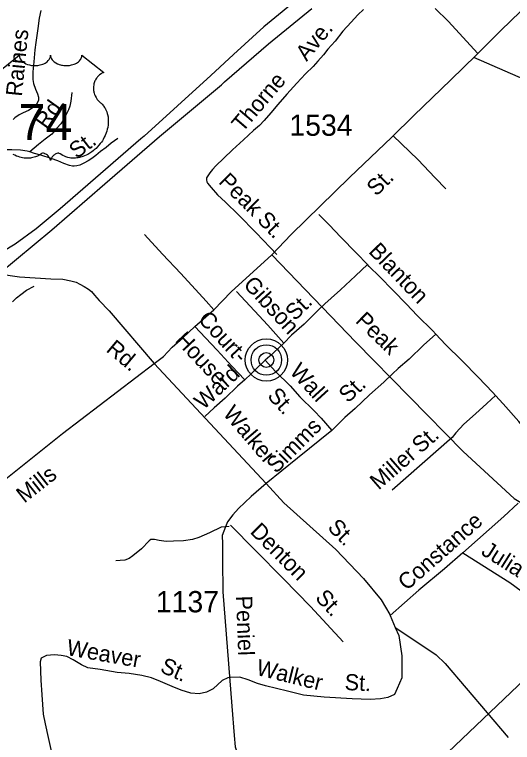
# Model space of a CAD drawing. Extents: x 990631 to 1056237, y 535999 to 585651.
# Drawn here: x 1044054 to 1046984, y 559473 to 563754 of the extents above; entities that cross this region are included whole.
import ezdxf

# ---------------------------------------------------------------- set-up
doc = ezdxf.new("R2010")
doc.units = 0
for name, color, linetype in [('Exist Boundary Political City Limit New', 7, 'Continuous'), ('Exist Civil Demographics County Seat CELL', 7, 'Continuous'), ('Exist Road Non-System Type 51', 7, 'Continuous'), ('Exist Road Non-System Type 51 Label', 7, 'Continuous'), ('Exist Road Primary NC Attributed', 7, 'Continuous'), ('Exist Road Primary NC Label', 7, 'Continuous'), ('Exist Road Primary US Divided Attributed', 7, 'Continuous'), ('Exist Road Primary US Shield CELL', 7, 'Continuous'), ('Exist Road Primary US Shield Number Label', 7, 'Continuous'), ('Exist Road Secondary Type 51 Attributed', 7, 'Continuous'), ('Exist Road Secondary Type 51 Label', 7, 'Continuous'), ('Exist Road Secondary Type 51 Number Label', 7, 'Continuous')]:
    doc.layers.add(name, color=color, linetype=linetype)

msp = doc.modelspace()

# ---------------------------------------------------------------- linework, layer by layer
at = {"layer": 'Exist Boundary Political City Limit New'}
msp.add_lwpolyline([(1047556.4, 560320.3), (1045570.9, 558429)], dxfattribs=at)
at = {"layer": 'Exist Civil Demographics County Seat CELL'}
for radius in [124.7, 90, 43.3]:
    msp.add_circle((1045536.1, 561722.3), radius, dxfattribs=at)
at = {"layer": 'Exist Road Non-System Type 51'}
for p, q in [((1046630.2, 561266.3), (1046276.1, 560957.5)), ((1046264.4, 560219.2), (1046294.2, 560148.2))]:
    msp.add_line(p, q, dxfattribs=at)
for points in [[(1046108.7, 563783.7), (1046073.7, 563752.8), (1046036.2, 563710), (1045986.5, 563655.5), (1045940.5, 563597), (1045898.9, 563550.3), (1045871.9, 563517.2), (1045838.7, 563480), (1045811.7, 563449), (1045766.2, 563404.5), (1045716.4, 563350), (1045656.3, 563285.8), (1045604.5, 563225.5), (1045562.9, 563176.7), (1045523.4, 563130), (1045496.4, 563100.8), (1045461.4, 563071.9), (1045401.7, 563017.8), (1045337.6, 562957.9), (1045286, 562909.5), (1045238.5, 562864.9), (1045219.9, 562843.4), (1045203.3, 562824), (1045188.6, 562800.4), (1045184.3, 562792.7), (1045184.1, 562782.7), (1045185.6, 562770.5), (1045189.3, 562762.4), (1045210.5, 562735.8), (1045249.1, 562694.6), (1045295.9, 562651), (1045371.4, 562576.5), (1045476.1, 562471.1), (1045559.4, 562384.2), (1045598.2, 562343)], [(1046780.6, 563524.3), (1046606.7, 563715.7), (1046529.2, 563790.3)], [(1044209.2, 563778.5), (1044199.8, 563732.9), (1044191.8, 563671), (1044179.2, 563589.4), (1044173.9, 563545.5), (1044167.5, 563475.6), (1044161.7, 563417.9), (1044162.2, 563371.9), (1044165.5, 563347.6), (1044178.4, 563315.1), (1044189.5, 563286.9), (1044194.9, 563268.6), (1044196.3, 563250.6), (1044189.9, 563236.9), (1044181.4, 563223), (1044169.1, 563211.5), (1044136.3, 563190.5), (1044105.8, 563175.5), (1044081.6, 563164.2), (1044056.8, 563147.1), (1044046.6, 563137.3)], [(1047929.9, 562160.1), (1047925.6, 562278.4), (1047914.2, 562426.9), (1047906.6, 562495.1), (1047901.4, 562527.4), (1047888.5, 562559.9), (1047868.4, 562614.5), (1047848.1, 562669.2), (1047825.6, 562717.8), (1047793.2, 562766.9), (1047756.8, 562816.2), (1047722.1, 562861.4), (1047695.1, 562890.3), (1047644.6, 562939.9), (1047587.9, 562985.7), (1047515.9, 563044.2), (1047437.7, 563106.6), (1047379.6, 563160.6), (1047319, 563210.6), (1047254.5, 563258.7), (1047207.6, 563294.1), (1047172.5, 563317.2), (1047125.1, 563340.7), (1046757.3, 563501.6)], [(1044391.9, 563296.4), (1044386.3, 563244.5), (1044379.3, 563214.7), (1044372.6, 563193), (1044357.7, 563165.5), (1044344.7, 563137.7), (1044326, 563110.3), (1044303.1, 563085.2), (1044273.9, 563049.9), (1044234.9, 563021.3), (1044195.9, 562990.5), (1044169.2, 562967.2), (1044144.6, 562946.1)], [(1044661.4, 563025.5), (1044622.4, 562996.9), (1044593.7, 562971.7), (1044560.8, 562948.7), (1044532.1, 562925.7), (1044509.6, 562908.3), (1044487.1, 562893), (1044462.6, 562879.9), (1044438.1, 562868.6), (1044420.1, 562865.1), (1044406, 562861.6), (1044396, 562862), (1044378.1, 562866.6), (1044344.5, 562877.6), (1044309, 562892.8), (1044269.5, 562908), (1044210, 562926), (1044172.2, 562937.1), (1044144.6, 562946.1)], [(1046593.1, 562729.4), (1046529.1, 562793.5), (1046426.7, 562900.8), (1046282.9, 563040.9)], [(1044144.6, 562946.1), (1044128.7, 562950.6), (1044088.8, 562955.8), (1044038.8, 562957.4), (1043992.8, 562958.9)], [(1046130.6, 562283.9), (1046066.7, 562350), (1045971.8, 562447.2), (1045907.9, 562515.3), (1045845.8, 562577.4)], [(1045227.6, 562017.3), (1045181.1, 562068.3), (1045032.1, 562231.2), (1044925.8, 562344.6), (1044819.5, 562460.1)], [(1046130.6, 562283.9), (1046060.4, 562218.1), (1045971.7, 562134.9), (1045918.1, 562086.7), (1045881, 562051.8)], [(1046533.7, 561874.7), (1046516.2, 561893.4), (1046423.2, 561984.3), (1046361.3, 562050.4), (1046281.7, 562131), (1046202.4, 562213.7), (1046142.1, 562271.5), (1046130.6, 562283.9)], [(1044042.3, 562064.8), (1044066.9, 562087.9), (1044091.5, 562107.2), (1044124.4, 562132.2), (1044169, 562156.5)], [(1045639.5, 561821.4), (1045544.8, 561926.6), (1045467.4, 562010.9), (1045360.9, 562124.5)], [(1045881, 562051.8), (1045839.8, 562013.1), (1045759.2, 561933.7), (1045685, 561867.9), (1045639.5, 561821.4)], [(1045410.5, 561606.5), (1045332.8, 561685.1), (1045245.9, 561779.9), (1045178.2, 561852.1), (1045114.7, 561918.4)], [(1046533.7, 561874.7), (1046461.5, 561809.1), (1046376.9, 561727.8), (1046311.1, 561671.7), (1046278.1, 561640.7)], [(1046884.3, 561513.3), (1046868.9, 561531.8), (1046781.8, 561620.6), (1046688.8, 561717.7), (1046589.8, 561812.9), (1046533.7, 561874.7)], [(1045639.5, 561821.4), (1045608.5, 561792.4), (1045556.9, 561744), (1045530, 561720.8)], [(1045530, 561720.8), (1045480.7, 561674.4), (1045447.6, 561641.4), (1045410.5, 561606.5)], [(1045530, 561720.8), (1045590.1, 561654.7), (1045675.4, 561570), (1045733.4, 561506.2), (1045816.7, 561423.5), (1045859.5, 561380), (1045921, 561307.4)], [(1045410.5, 561606.5), (1045367.1, 561568), (1045292.9, 561498.3), (1045228.9, 561440.3), (1045174.7, 561389.5)], [(1046278.1, 561640.7), (1046228.5, 561592.3), (1046143.9, 561517), (1046059.3, 561437.6), (1045997.6, 561383.7), (1045921, 561307.4)], [(1046884.3, 561513.3), (1046832.8, 561466.9), (1046766.9, 561405), (1046698.9, 561345.1), (1046651.3, 561293.2), (1046630.2, 561266.3)], [(1047265.7, 561109.8), (1047202.5, 561139.9), (1047144.7, 561211.7), (1047089.1, 561278.9), (1047021.5, 561360.7), (1046930.7, 561463.7), (1046884.3, 561513.3)], [(1045921, 561307.4), (1045720.1, 561145.2), (1045534.2, 560996.2)], [(1045534.2, 560996.2), (1045639.2, 560881.4), (1045944.7, 560607.8), (1046107.3, 560436.5), (1046211.3, 560311.2), (1046262.5, 560225.3), (1046264.4, 560219.2)], [(1047018.2, 560879.5), (1046933.6, 560802.2), (1046692.6, 560587.8)], [(1045989.2, 560063.9), (1045795.7, 560272.3), (1045637, 560435.6), (1045470.3, 560603), (1045324.8, 560751.8)], [(1045316.6, 560742.1), (1045270.4, 560739.5), (1045201.3, 560705.6), (1045138.5, 560677.7), (1045102, 560666.8), (1045047.7, 560658.7), (1044989.6, 560656.5), (1044947.6, 560655.7), (1044905.7, 560661.2), (1044877.8, 560666.1), (1044855.8, 560666.8), (1044847.6, 560659.1), (1044802, 560612.4), (1044750.8, 560570.1), (1044728.1, 560554.7), (1044703.9, 560545.6), (1044675.8, 560542.4), (1044649.8, 560541.3)], [(1046692.6, 560587.8), (1046585.5, 560493.3), (1046433.3, 560368.1), (1046264.4, 560219.2)], [(1046692.6, 560587.8), (1046969.2, 560412.9), (1047102.1, 560316.6), (1047147.4, 560293.1), (1047213.1, 560285), (1047317.4, 560287.7), (1047365.6, 560298.1), (1047418.5, 560322.5), (1047451.1, 560341.4)], [(1046294.2, 560148.2), (1046316.7, 560101.6), (1046332.9, 559983), (1046332.7, 559852.9), (1046306.6, 559789.6), (1046289.5, 559754.2), (1046250.9, 559737.3), (1046208.7, 559728.8), (1046146.4, 559724.8), (1046040.7, 559730.2), (1045876.8, 559739.5), (1045755, 559751.3), (1045659.9, 559774.5), (1045530.7, 559806.5), (1045485.1, 559820), (1045429.7, 559841.7), (1045380.2, 559857.3), (1045326.2, 559855.2)], [(1046294.2, 560148.2), (1046451, 560045.2), (1046535.3, 559988.5), (1046587.6, 559936.8), (1046959.8, 559502.6)], [(1045326.2, 559855.2), (1045310.1, 559853.7), (1045275.6, 559836.8), (1045224, 559788.4), (1045183.2, 559769.7), (1045141, 559759.1), (1045091, 559762.7), (1045035.6, 559780.4), (1044982.2, 559802.1), (1044913.2, 559832.3), (1044859.7, 559852.2), (1044804.2, 559865.9), (1044728.4, 559878.2), (1044658.5, 559884.5), (1044559, 559901.9), (1044485.4, 559912.2), (1044448, 559929.3), (1044398.9, 559958.9), (1044361.5, 559978.1), (1044329.6, 559985.1), (1044289.7, 559988.5), (1044241.6, 559984.1), (1044211.1, 559968.9), (1044204.4, 559947.2), (1044208.9, 559838.9), (1044214.1, 559752.8), (1044222.5, 559640.3), (1044234.7, 559581.9), (1044252.1, 559501.3), (1044271.3, 559414.7)]]:
    msp.add_lwpolyline(points, dxfattribs=at)
at = {"layer": 'Exist Road Primary NC Attributed'}
for points in [[(1045567.7, 562340.2), (1045682.5, 562460.5), (1046025, 562795.1), (1046274.5, 563032.6), (1046404.6, 563160.8), (1046621.7, 563370.6), (1046771.4, 563515), (1046901.5, 563647.2), (1046989.2, 563730.8), (1047131.4, 563866.4), (1047185.4, 563916.4), (1047237.5, 563962.6)], [(1044875.9, 561701), (1044930.6, 561743.3), (1044982.7, 561798.2), (1045045.6, 561852.1), (1045114.7, 561918.4), (1045227.6, 562017.3), (1045330.1, 562124.1), (1045567.7, 562340.2)], [(1043264.1, 560006.8), (1043301.1, 560087.7), (1043356.2, 560202.3), (1043396.6, 560300.1), (1043465.9, 560437.4), (1043488.5, 560482.8), (1043571.2, 560612), (1043623.3, 560676.2), (1043729.6, 560794.1), (1043834.2, 560890.3), (1044336.7, 561290.9), (1044875.9, 561701)]]:
    msp.add_lwpolyline(points, dxfattribs=at)
at = {"layer": 'Exist Road Primary US Divided Attributed'}
for points in [[(1045749.4, 563870.6), (1045521.5, 563680.7), (1045342.9, 563519.8), (1045208.9, 563394.6), (1044818, 563039.3), (1044797.9, 563023.6), (1044322.5, 562611.4), (1044182.1, 562494), (1044059, 562403.5), (1043823.6, 562261.7)], [(1043960.7, 562229.1), (1044274.8, 562488.4), (1044585.7, 562757.7), (1044907.3, 563037.1), (1045271.4, 563341), (1045289.3, 563358.9), (1045548.3, 563582.4), (1045803, 563790.2)]]:
    msp.add_lwpolyline(points, dxfattribs=at)
at = {"layer": 'Exist Road Primary US Shield CELL'}
msp.add_lwpolyline([(1043953.8, 563412.5), (1044082.4, 563515), (1044082.7, 563509.6), (1044084, 563503.3), (1044085, 563500.1), (1044088, 563493.8), (1044092.8, 563486.5), (1044099.6, 563479.3), (1044107.3, 563472.9), (1044112.4, 563469.6), (1044121.2, 563464.9), (1044131.2, 563460.7), (1044142.3, 563457.5), (1044153.6, 563455.2), (1044165.9, 563453.9), (1044178.2, 563453.6), (1044191.4, 563454.6), (1044206, 563457.4), (1044212.7, 563459.2), (1044220.3, 563461.8), (1044227.2, 563464.7), (1044234.9, 563468.8), (1044241.1, 563472.7), (1044245.9, 563476.2), (1044252.7, 563482.7), (1044258.2, 563489.5), (1044260.4, 563493.3), (1044262.4, 563497), (1044265.1, 563504.7), (1044265.9, 563508.1), (1044266.4, 563515.2), (1044266.8, 563509.3), (1044267.5, 563505.5), (1044268.4, 563501.9), (1044270, 563498), (1044272.7, 563492.5), (1044275.7, 563488), (1044281.5, 563481.2), (1044285, 563477.9), (1044288.3, 563475.2), (1044297, 563469.2), (1044307.2, 563464.1), (1044312.3, 563461.9), (1044317.4, 563460), (1044324, 563458.1), (1044330.7, 563456.5), (1044337.4, 563455.3), (1044344.2, 563454.3), (1044351.2, 563453.8), (1044356.9, 563453.6), (1044363.9, 563453.7), (1044370.4, 563454.1), (1044377, 563454.9), (1044384.3, 563456.1), (1044390.1, 563457.4), (1044397.9, 563459.4), (1044404.8, 563461.9), (1044411, 563464.6), (1044419, 563468.8), (1044425.4, 563472.8), (1044430.1, 563476.6), (1044435.8, 563481.8), (1044441.1, 563487.9), (1044444.2, 563492.4), (1044446.4, 563497), (1044448.4, 563501.9), (1044449.7, 563507.1), (1044450.3, 563511.5), (1044450.4, 563515.4), (1044579, 563412.9), (1044576, 563411.8), (1044569, 563408.4), (1044563.5, 563405.1), (1044554.6, 563398.9), (1044550.8, 563395.4), (1044547, 563391.9), (1044543.5, 563388.1), (1044540.4, 563384.5), (1044536.7, 563379.3), (1044533.4, 563374.2), (1044530.1, 563368.5), (1044527.7, 563363.5), (1044523.8, 563353.2), (1044521.9, 563346.7), (1044520.7, 563341.1), (1044519.1, 563329.6), (1044518.8, 563324.2), (1044518.8, 563318.8), (1044519.1, 563313.1), (1044519.6, 563307.6), (1044520.6, 563301.9), (1044521.5, 563296.9), (1044523.1, 563290.7), (1044525.4, 563283.6), (1044528.2, 563276.7), (1044534.1, 563265.5), (1044541.6, 563254.1), (1044547, 563247.7), (1044552.3, 563242.2), (1044560.3, 563235.6), (1044564.6, 563231.8), (1044569.5, 563226.8), (1044577.5, 563217.5), (1044580.8, 563213.1), (1044584.1, 563208.1), (1044587.2, 563203), (1044590.2, 563197.6), (1044592.6, 563192.8), (1044597.1, 563181.8), (1044600.4, 563171), (1044602, 563165.4), (1044604.4, 563152.8), (1044605.3, 563146.6), (1044606.3, 563134.3), (1044606.3, 563119.4), (1044605.2, 563105.2), (1044602.5, 563088.8), (1044600.3, 563078.9), (1044596.9, 563067.4), (1044593.6, 563057.4), (1044587.8, 563042.8), (1044582.6, 563032.1), (1044575.8, 563019.7), (1044571.2, 563012.2), (1044565.8, 563004.1), (1044559, 562994.8), (1044551.1, 562985), (1044541.6, 562974.5), (1044534, 562966.9), (1044523.9, 562957.9), (1044517.9, 562952.9), (1044509.2, 562946.4), (1044497.3, 562938.5), (1044485.7, 562931.7), (1044475.7, 562926.6), (1044466.9, 562922.8), (1044455.5, 562918.5), (1044436.5, 562913.2), (1044429.6, 562911.8), (1044421.4, 562910.6), (1044413.7, 562909.8), (1044406.3, 562909.3), (1044396.3, 562909.3), (1044386.3, 562910.1), (1044376.9, 562911.5), (1044367.1, 562913.5), (1044356.8, 562916.6), (1044347.5, 562920.2), (1044338.1, 562924.9), (1044322.2, 562934.9), (1044317.6, 562937.3), (1044315, 562938), (1044308.9, 562938.3), (1044303.1, 562937.1), (1044297.2, 562934.7), (1044293.6, 562932.8), (1044288.9, 562929.7), (1044285.2, 562926.8), (1044280.8, 562922.6), (1044277.8, 562919.1), (1044275.5, 562916.4), (1044271, 562909.3), (1044269.4, 562906), (1044267.7, 562901.7), (1044266.3, 562895.3), (1044264.2, 562903.3), (1044261.9, 562908.7), (1044259.1, 562913.2), (1044256.3, 562917.3), (1044251.8, 562922.4), (1044247.8, 562926.3), (1044242.9, 562930.2), (1044237.8, 562933.4), (1044233.6, 562935.5), (1044229.8, 562936.9), (1044225.2, 562938.1), (1044221.4, 562938.4), (1044218.3, 562938.3), (1044214, 562937.3), (1044208.2, 562933.1), (1044202.7, 562929.3), (1044196.7, 562925.6), (1044189.5, 562921.8), (1044184.3, 562919.4), (1044178.1, 562916.9), (1044170.8, 562914.5), (1044162.9, 562912.5), (1044154.7, 562910.9), (1044147.6, 562909.7), (1044139.9, 562909), (1044133, 562908.8), (1044125.8, 562908.9), (1044119.1, 562909.4), (1044111.2, 562910.1), (1044101.5, 562911.5), (1044093.5, 562913.4), (1044085, 562915.7), (1044076.2, 562918.4), (1044066.9, 562922), (1044055.2, 562927.1), (1044047.1, 562931.2)], dxfattribs=at)
at = {"layer": 'Exist Road Secondary Type 51 Attributed'}
for points in [[(1045567.7, 562340.2), (1046062.7, 561826.7), (1046694.8, 561184.1), (1046993.8, 560907.5), (1047477.1, 560615.2), (1047515.6, 560594), (1047562.1, 560574), (1047603.3, 560560.8), (1047644.4, 560556.8), (1047713.5, 560555.4), (1047794.5, 560563.4), (1047922.3, 560597), (1048119.7, 560656.3), (1048220.7, 560685), (1048349.4, 560726.8), (1048417.2, 560744.1), (1048479.2, 560758.7)], [(1043960.7, 562229.1), (1044083.2, 562211.1), (1044174.8, 562205.5), (1044268.6, 562199.3), (1044337.7, 562197.6), (1044385.5, 562188.1), (1044417.5, 562179.6), (1044439.4, 562167.8), (1044464.1, 562153.8), (1044490, 562138.6), (1044507.5, 562125.6), (1044525.8, 562103.3), (1044552.8, 562072.3), (1044610.7, 562010.6), (1044875.9, 561701)], [(1044875.9, 561701), (1045534.2, 560996.2), (1045447.6, 560919.2), (1045373.1, 560849.4), (1045338.2, 560812.1), (1045308.1, 560770), (1045294.9, 560741.2), (1045276.8, 560689.3), (1045277.4, 560641.3), (1045278.2, 560543.2), (1045280, 560359.3), (1045332.8, 559686.8), (1045347.1, 559513.5), (1045353.6, 559446.4), (1045374.9, 559381), (1045430.5, 559317.2), (1046767.2, 558240.6)]]:
    msp.add_lwpolyline(points, dxfattribs=at)

# ---------------------------------------------------------------- texts
at = {"layer": 'Exist Road Non-System Type 51 Label'}
for s, rotation, p in [('Raines', 84.298, (1044097.4, 563269.5)), ('Ave.', 50.6924, (1045773.3, 563474.5)), ('Thorne', 49.547, (1045395.6, 563056.3)), ('Rd.', 54.4545, (1044242.7, 563074.5)), ('St.', 37.5717, (1044421, 562902.3)), ('Peak', 315.3742, (1045249.9, 562765.5)), ('St.', 313.7791, (1045476.5, 562541.8)), ('Blanton', 313.8467, (1046132.9, 562357)), ('Gibson', 312.5013, (1045395.6, 562162.2)), ('St.', 44.5654, (1045703.8, 561948.2)), ('Court-', 312.5234, (1045129.6, 561957.6)), ('Peak', 315.8873, (1046055.1, 561947.1)), ('House', 313.1921, (1044994.5, 561834.4)), ('Ward', 43.2513, (1045166.4, 561424.8)), ('Wall', 312.2475, (1045668.7, 561650.6)), ('St.', 43.1507, (1046016.5, 561464.9)), ('St.', 312.2475, (1045537.2, 561507.7)), ('Walker', 310.4074, (1045276.4, 561404.8)), ('Simms', 44.9403, (1045593.7, 561050.3)), ('St.', 41.0858, (1046443.7, 561168.9)), ('Miller', 41.0858, (1046197, 560953.8)), ('Constance', 41.4061, (1046361.9, 560361.7)), ('Denton', 314.8744, (1045435.4, 560707.8)), ('St.', 314.6221, (1045891.2, 560732.1)), ('Julia', 327.7013, (1046794.6, 560581.5)), ('St.', 312.876, (1045818.7, 560319.9)), ('Weaver', 350.0742, (1044356.5, 559987.3)), ('St.', 336.3664, (1044905, 559889.6)), ('Walker', 346.0833, (1045471, 559871.9)), ('St.', 357.1137, (1045995.4, 559781.7))]:
    msp.add_text(s, height=95, rotation=rotation, dxfattribs=at).set_placement(p)
at = {"layer": 'Exist Road Primary NC Label'}
for s, rotation, p in [('St.', 44.8909, (1046183.4, 562680.8)), ('Mills', 38.3143, (1044112, 560876.7))]:
    msp.add_text(s, height=95, rotation=rotation, dxfattribs=at).set_placement(p)
at = {"layer": 'Exist Road Primary US Shield Number Label'}
msp.add_text('74', height=212.5, dxfattribs=at).set_placement((1044078.1, 563015.7))
at = {"layer": 'Exist Road Secondary Type 51 Label'}
for s, rotation, p in [('Rd.', 320.2372, (1044587.6, 561776)), ('Peniel', 272.1271, (1045357.7, 560334.6))]:
    msp.add_text(s, height=95, rotation=rotation, dxfattribs=at).set_placement(p)
at = {"layer": 'Exist Road Secondary Type 51 Number Label'}
for s, p in [('1534', (1045671.7, 563040.8)), ('1137', (1044885.7, 560238.4))]:
    msp.add_text(s, height=125, dxfattribs=at).set_placement(p)

doc.saveas('drawing.dxf')
